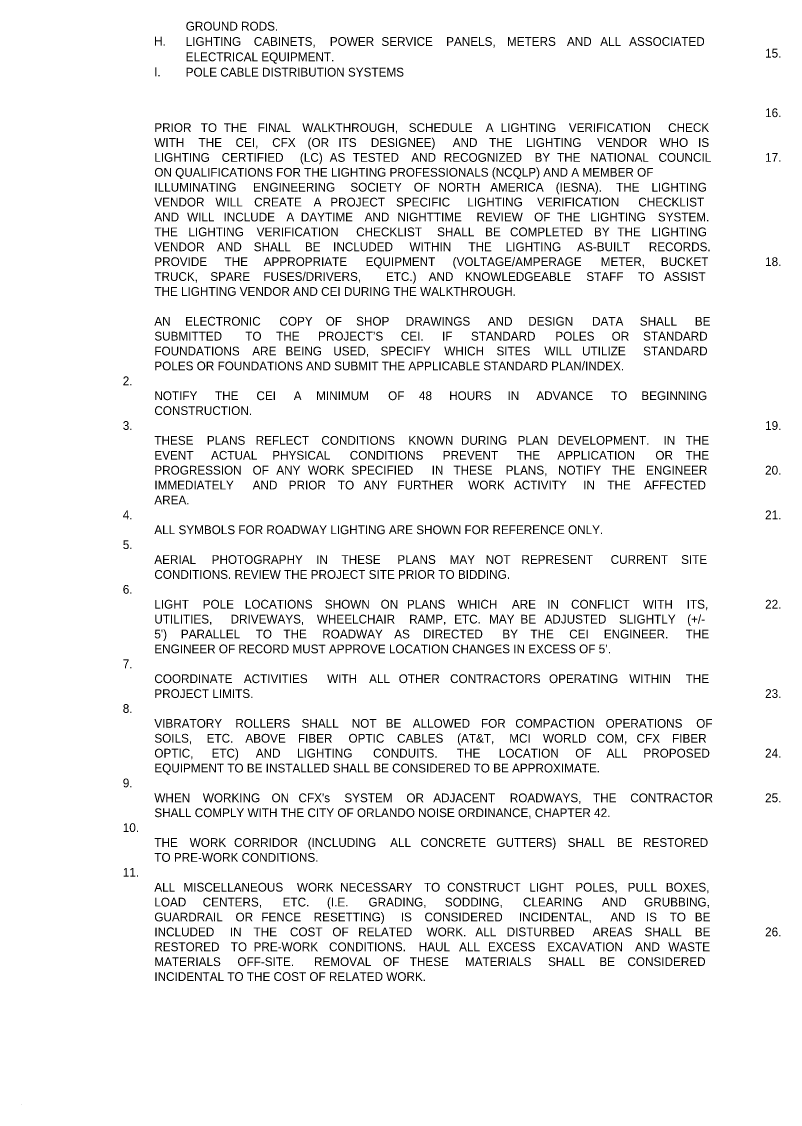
# Model space of a CAD drawing. Extents: x -55 to 2471539, y -90 to 3608906.
# Drawn here: x -55 to 551, y -90 to 775 of the extents above; entities that cross this region are included whole.
import ezdxf

# ---------------------------------------------------------------- set-up
doc = ezdxf.new("R2010")
doc.units = 0
doc.layers.add('TextMinor', color=7, linetype='Continuous')
doc.layers.add('XSCell', color=7, linetype='Continuous')

msp = doc.modelspace()

# ---------------------------------------------------------------- linework, layer by layer
at = {"layer": 'TextMinor'}
msp.add_line((-55, -90), (-55, -90), dxfattribs=at)

# ---------------------------------------------------------------- texts
at = {"layer": 'XSCell'}
for s, p in [('GROUND RODS.', (75.97, 767.96)), ('H.', (50.72, 755.98)), ('LIGHTING ', (75.97, 755.71)), ('CABINETS, ', (130.32, 755.71)), ('POWER ', (191.04, 755.71)), ('SERVICE ', (232.19, 755.71)), ('PANELS, ', (283.88, 755.71)), ('METERS ', (332.46, 755.71)), ('AND ', (380.33, 755.71)), ('ALL ', (406.91, 755.71)), ('ASSOCIATED ', (429.97, 755.71)), ('15.', (538.51, 746.38)), ('ELECTRICAL EQUIPMENT.', (75.97, 743.46)), ('I.', (50.72, 731.48)), ('POLE CABLE DISTRIBUTION SYSTEMS', (75.97, 731.21)), ('16.', (538.51, 698.78)), ('PRIOR ', (50.92, 686.88)), ('TO ', (87.97, 686.88)), ('THE ', (106.26, 686.88)), ('FINAL ', (133.38, 686.88)), ('WALKTHROUGH, ', (169.06, 686.88)), ('SCHEDULE ', (254.01, 686.88)), ('A ', (315.47, 686.88)), ('LIGHTING ', (327.43, 686.88)), ('VERIFICATION ', (381.77, 686.88)), ('CHECK ', (461.12, 686.88)), ('WITH ', (50.92, 674.98)), ('THE ', (86.21, 674.98)), ('CEI, ', (115.75, 674.98)), ('CFX ', (145, 674.98)), ('(OR ', (173.26, 674.98)), ('ITS ', (197.82, 674.98)), ('DESIGNEE) ', (223.77, 674.98)), ('AND ', (289.13, 674.98)), ('THE ', (318.13, 674.98)), ('LIGHTING ', (347.67, 674.98)), ('VENDOR ', (404.44, 674.98)), ('WHO ', (454.24, 674.98)), ('IS ', (484.99, 674.98)), ('LIGHTING ', (50.92, 663.08)), ('CERTIFIED ', (104.66, 663.08)), ('(LC) ', (167.14, 663.08)), ('AS ', (190.89, 663.08)), ('TESTED ', (209.32, 663.08)), ('AND ', (256.04, 663.08)), ('RECOGNIZED ', (282.02, 663.08)), ('BY ', (354.46, 663.08)), ('THE ', (372.41, 663.08)), ('NATIONAL ', (398.92, 663.08)), ('COUNCIL ', (453.39, 663.08)), ('17.', (538.51, 663.08)), ('ON QUALIFICATIONS FOR THE LIGHTING PROFESSIONALS (NCQLP) AND A MEMBER OF ', (50.92, 651.18)), ('ILLUMINATING ', (50.92, 639.28)), ('ENGINEERING ', (129.76, 639.28)), ('SOCIETY ', (207.39, 639.28)), ('OF ', (258.02, 639.28)), ('NORTH ', (277.76, 639.28)), ('AMERICA ', (319.04, 639.28)), ('(IESNA). ', (371.35, 639.28)), ('THE ', (419.56, 639.28)), ('LIGHTING ', (447.79, 639.28)), ('VENDOR ', (50.92, 627.38)), ('WILL ', (99.69, 627.38)), ('CREATE ', (130.61, 627.38)), ('A ', (178.05, 627.38)), ('PROJECT ', (191.4, 627.38)), ('SPECIFIC ', (243.88, 627.38)), ('LIGHTING ', (300.8, 627.38)), ('VERIFICATION ', (356.54, 627.38)), ('CHECKLIST ', (437.29, 627.38)), ('AND ', (50.92, 615.48)), ('WILL ', (77.06, 615.48)), ('INCLUDE ', (106.15, 615.48)), ('A ', (156.37, 615.48)), ('DAYTIME ', (167.89, 615.48)), ('AND ', (218.8, 615.48)), ('NIGHTTIME ', (244.95, 615.48)), ('REVIEW ', (308.14, 615.48)), ('OF ', (354.11, 615.48)), ('THE ', (372.31, 615.48)), ('LIGHTING ', (399, 615.48)), ('SYSTEM. ', (452.91, 615.48)), ('THE ', (50.92, 603.58)), ('LIGHTING ', (78.14, 603.58)), ('VERIFICATION ', (132.59, 603.58)), ('CHECKLIST ', (212.05, 603.58)), ('SHALL ', (276.7, 603.58)), ('BE ', (315.01, 603.58)), ('COMPLETED ', (334.87, 603.58)), ('BY ', (401.91, 603.58)), ('THE ', (420.57, 603.58)), ('LIGHTING ', (447.79, 603.58)), ('VENDOR ', (50.92, 591.68)), ('AND ', (100.99, 591.68)), ('SHALL ', (130.26, 591.68)), ('BE ', (171.16, 591.68)), ('INCLUDED ', (193.6, 591.68)), ('WITHIN ', (254.63, 591.68)), ('THE ', (301.66, 591.68)), ('LIGHTING ', (331.48, 591.68)), ('AS-BUILT ', (388.52, 591.68)), ('RECORDS. ', (445.65, 591.68)), ('PROVIDE ', (50.92, 579.78)), ('THE ', (106.93, 579.78)), ('APPROPRIATE ', (138.23, 579.78)), ('EQUIPMENT ', (219.54, 579.78)), ('(VOLTAGE/AMPERAGE ', (289.04, 579.78)), ('METER, ', (407.26, 579.78)), ('BUCKET ', (455.29, 579.78)), ('18.', (538.51, 579.78)), ('TRUCK, ', (50.92, 567.88)), ('SPARE ', (95.61, 567.88)), ('FUSES/DRIVERS, ', (137.94, 567.88)), ('ETC.) ', (235.78, 567.88)), ('AND ', (269.92, 567.88)), ('KNOWLEDGEABLE ', (298.92, 567.88)), ('STAFF ', (395.78, 567.88)), ('TO ', (437.04, 567.88)), ('ASSIST ', (457.75, 567.88)), ('THE LIGHTING VENDOR AND CEI DURING THE WALKTHROUGH. ', (50.92, 555.98)), ('AN ', (50.92, 532.18)), ('ELECTRONIC ', (75.49, 532.18)), ('COPY ', (150.75, 532.18)), ('OF ', (187.7, 532.18)), ('SHOP ', (212.01, 532.18)), ('DRAWINGS ', (251.62, 532.18)), ('AND ', (317.13, 532.18)), ('DESIGN ', (349.39, 532.18)), ('DATA ', (400.39, 532.18)), ('SHALL ', (438.51, 532.18)), ('BE ', (482.39, 532.18)), ('SUBMITTED ', (50.92, 520.28)), ('TO ', (123.51, 520.28)), ('THE ', (148.15, 520.28)), ('PROJECT’S ', (181.63, 520.28)), ('CEI. ', (247.7, 520.28)), ('IF ', (280.58, 520.28)), ('STANDARD ', (303.72, 520.28)), ('POLES ', (371.09, 520.28)), ('OR ', (415.99, 520.28)), ('STANDARD ', (441.13, 520.28)), ('FOUNDATIONS ', (50.92, 508.38)), ('ARE ', (129.11, 508.38)), ('BEING ', (155.61, 508.38)), ('USED, ', (193.77, 508.38)), ('SPECIFY ', (231.5, 508.38)), ('WHICH ', (282.39, 508.38)), ('SITES ', (324.05, 508.38)), ('WILL ', (362.31, 508.38)), ('UTILIZE ', (392.36, 508.38)), ('STANDARD ', (441.13, 508.38)), ('POLES OR FOUNDATIONS AND SUBMIT THE APPLICABLE STANDARD PLAN/INDEX.', (50.92, 496.48)), ('2.', (25.72, 484.58)), ('NOTIFY ', (50.92, 472.68)), ('THE ', (99.31, 472.68)), ('CEI ', (132.42, 472.68)), ('A ', (162.18, 472.68)), ('MINIMUM ', (180.13, 472.68)), ('OF ', (237.55, 472.68)), ('48 ', (262.17, 472.68)), ('HOURS ', (286.27, 472.68)), ('IN ', (332.9, 472.68)), ('ADVANCE ', (355.9, 472.68)), ('TO ', (415.42, 472.68)), ('BEGINNING ', (439.69, 472.68)), ('CONSTRUCTION.', (50.92, 460.78)), ('3.', (25.72, 448.88)), ('19.', (538.51, 448.88)), ('THESE ', (50.92, 436.98)), ('PLANS ', (92.83, 436.98)), ('REFLECT ', (131.8, 436.98)), ('CONDITIONS ', (184.27, 436.98)), ('KNOWN ', (253.77, 436.98)), ('DURING ', (295.65, 436.98)), ('PLAN ', (340.92, 436.98)), ('DEVELOPMENT. ', (372.81, 436.98)), ('IN ', (457.44, 436.98)), ('THE ', (475.03, 436.98)), ('EVENT ', (50.92, 425.08)), ('ACTUAL ', (96.2, 425.08)), ('PHYSICAL ', (145.08, 425.08)), ('CONDITIONS ', (206.94, 425.08)), ('PREVENT ', (281.18, 425.08)), ('THE ', (340.2, 425.08)), ('APPLICATION ', (372.64, 425.08)), ('OR ', (450.92, 425.08)), ('THE ', (475.03, 425.08)), ('PROGRESSION ', (50.92, 413.18)), ('OF ', (129.35, 413.18)), ('ANY ', (148.35, 413.18)), ('WORK ', (173.54, 413.18)), ('SPECIFIED ', (208.2, 413.18)), ('IN ', (272.35, 413.18)), ('THESE ', (289.73, 413.18)), ('PLANS, ', (331.43, 413.18)), ('NOTIFY ', (373.24, 413.18)), ('THE ', (416.02, 413.18)), ('ENGINEER ', (443.5, 413.18)), ('20.', (538.51, 413.18)), ('IMMEDIATELY ', (50.92, 401.28)), ('AND ', (129.41, 401.28)), ('PRIOR ', (158.2, 401.28)), ('TO ', (197.46, 401.28)), ('ANY ', (217.96, 401.28)), ('FURTHER ', (244.99, 401.28)), ('WORK ', (301.5, 401.28)), ('ACTIVITY ', (338.01, 401.28)), ('IN ', (393.31, 401.28)), ('THE ', (412.53, 401.28)), ('AFFECTED ', (441.86, 401.28)), ('AREA.', (50.92, 389.38)), ('4.', (25.72, 377.48)), ('21.', (538.51, 377.48)), ('ALL SYMBOLS FOR ROADWAY LIGHTING ARE SHOWN FOR REFERENCE ONLY.', (50.92, 365.58)), ('5.', (25.72, 353.68)), ('AERIAL ', (50.92, 341.78)), ('PHOTOGRAPHY ', (96.65, 341.78)), ('IN ', (180.07, 341.78)), ('THESE ', (200.35, 341.78)), ('PLANS ', (244.95, 341.78)), ('MAY ', (286.61, 341.78)), ('NOT ', (315.49, 341.78)), ('REPRESENT ', (343.98, 341.78)), ('CURRENT ', (415.21, 341.78)), ('SITE ', (471.49, 341.78)), ('CONDITIONS. REVIEW THE PROJECT SITE PRIOR TO BIDDING.', (50.92, 329.88)), ('6.', (25.72, 317.98)), ('LIGHT ', (50.92, 306.08)), ('POLE ', (89.54, 306.08)), ('LOCATIONS ', (123.15, 306.08)), ('SHOWN ', (187.03, 306.08)), ('ON ', (231.54, 306.08)), ('PLANS ', (252.54, 306.08)), ('WHICH ', (293.07, 306.08)), ('ARE ', (336.35, 306.08)), ('IN ', (364.47, 306.08)), ('CONFLICT ', (383.63, 306.08)), ('WITH ', (440.93, 306.08)), ('ITS, ', (475.95, 306.08)), ('22.', (538.51, 306.08)), ('UTILITIES, ', (50.92, 294.18)), ('DRIVEWAYS, ', (111.78, 294.18)), ('WHEELCHAIR ', (180.68, 294.18)), ('RAMP, ', (254.36, 294.18)), ('ETC. ', (290.3, 294.18)), ('MAY ', (318.12, 294.18)), ('BE ', (343.19, 294.18)), ('ADJUSTED ', (362.4, 294.18)), ('SLIGHTLY ', (421.83, 294.18)), ('(+/- ', (476.32, 294.18)), ("5') ", (50.92, 282.28)), ('PARALLEL ', (72.07, 282.28)), ('TO ', (131.83, 282.28)), ('THE ', (153.99, 282.28)), ('ROADWAY ', (184.97, 282.28)), ('AS ', (242.43, 282.28)), ('DIRECTED ', (265.33, 282.28)), ('BY ', (328.73, 282.28)), ('THE ', (351.14, 282.28)), ('CEI ', (382.13, 282.28)), ('ENGINEER. ', (409.76, 282.28)), ('THE ', (475.03, 282.28)), ('ENGINEER OF RECORD MUST APPROVE LOCATION CHANGES IN EXCESS OF 5’.', (50.92, 270.38)), ('7.', (25.72, 258.48)), ('COORDINATE ', (50.92, 246.58)), ('ACTIVITIES ', (122.34, 246.58)), ('WITH ', (188.86, 246.58)), ('ALL ', (222.36, 246.58)), ('OTHER ', (246.03, 246.58)), ('CONTRACTORS ', (287.02, 246.58)), ('OPERATING ', (365.99, 246.58)), ('WITHIN ', (430.06, 246.58)), ('THE ', (475.03, 246.58)), ('PROJECT LIMITS.', (50.92, 234.68)), ('23.', (538.51, 234.68)), ('8.', (25.72, 222.78)), ('VIBRATORY ', (50.92, 210.88)), ('ROLLERS ', (115.6, 210.88)), ('SHALL ', (168.44, 210.88)), ('NOT ', (208.51, 210.88)), ('BE ', (235.59, 210.88)), ('ALLOWED ', (257.21, 210.88)), ('FOR ', (311.68, 210.88)), ('COMPACTION ', (339.05, 210.88)), ('OPERATIONS ', (411.16, 210.88)), ('OF ', (483.52, 210.88)), ('SOILS, ', (50.92, 198.98)), ('ETC. ', (92.67, 198.98)), ('ABOVE ', (123.59, 198.98)), ('FIBER ', (165.51, 198.98)), ('OPTIC ', (205.94, 198.98)), ('CABLES ', (244.74, 198.98)), ('(AT&T, ', (292.64, 198.98)), ('MCI ', (334.23, 198.98)), ('WORLD ', (361.13, 198.98)), ('COM, ', (404.06, 198.98)), ('CFX ', (435.87, 198.98)), ('FIBER ', (464.26, 198.98)), ('OPTIC, ', (50.92, 187.08)), ('ETC) ', (96.58, 187.08)), ('AND ', (131.91, 187.08)), ('LIGHTING ', (164.85, 187.08)), ('CONDUITS. ', (225.56, 187.08)), ('THE ', (292.46, 187.08)), ('LOCATION ', (325.94, 187.08)), ('OF ', (386.95, 187.08)), ('ALL ', (411.94, 187.08)), ('PROPOSED ', (441.35, 187.08)), ('24.', (538.51, 187.08)), ('EQUIPMENT TO BE INSTALLED SHALL BE CONSIDERED TO BE APPROXIMATE.', (50.92, 175.18)), ('9.', (25.72, 163.28)), ('WHEN ', (50.92, 151.38)), ('WORKING ', (89.63, 151.38)), ('ON ', (144.47, 151.38)), ("CFX's ", (166, 151.38)), ('SYSTEM ', (202.59, 151.38)), ('OR ', (252.13, 151.38)), ('ADJACENT ', (273.59, 151.38)), ('ROADWAYS, ', (334.69, 151.38)), ('THE ', (401.09, 151.38)), ('CONTRACTOR ', (430.88, 151.38)), ('25.', (538.51, 151.38)), ('SHALL COMPLY WITH THE CITY OF ORLANDO NOISE ORDINANCE, CHAPTER 42.', (50.92, 139.48)), ('10.', (25.72, 127.58)), ('THE ', (50.92, 115.68)), ('WORK ', (79.14, 115.68)), ('CORRIDOR ', (114.54, 115.68)), ('(INCLUDING ', (173.34, 115.68)), ('ALL ', (239.19, 115.68)), ('CONCRETE ', (263.34, 115.68)), ('GUTTERS) ', (323.94, 115.68)), ('SHALL ', (380.9, 115.68)), ('BE ', (420.21, 115.68)), ('RESTORED ', (441.07, 115.68)), ('TO PRE-WORK CONDITIONS.', (50.92, 103.78)), ('11.', (25.72, 91.88)), ('ALL ', (50.92, 79.98)), ('MISCELLANEOUS ', (74.2, 79.98)), ('WORK ', (164.73, 79.98)), ('NECESSARY ', (199.25, 79.98)), ('TO ', (266.17, 79.98)), ('CONSTRUCT ', (284.68, 79.98)), ('LIGHT ', (350.29, 79.98)), ('POLES, ', (386.99, 79.98)), ('PULL ', (428.81, 79.98)), ('BOXES, ', (459.25, 79.98)), ('LOAD ', (50.92, 68.08)), ('CENTERS, ', (89.55, 68.08)), ('ETC. ', (153.33, 68.08)), ('(I.E. ', (188.77, 68.08)), ('GRADING, ', (221.91, 68.08)), ('SODDING, ', (282.85, 68.08)), ('CLEARING ', (345.23, 68.08)), ('AND ', (408.25, 68.08)), ('GRUBBING, ', (441.91, 68.08)), ('GUARDRAIL ', (50.92, 56.18)), ('OR ', (115.72, 56.18)), ('FENCE ', (136.3, 56.18)), ('RESETTING) ', (178.12, 56.18)), ('IS ', (247.66, 56.18)), ('CONSIDERED ', (266.61, 56.18)), ('INCIDENTAL, ', (341.94, 56.18)), ('AND ', (414.99, 56.18)), ('IS ', (443.37, 56.18)), ('TO ', (462.31, 56.18)), ('BE ', (482.39, 56.18)), ('INCLUDED ', (50.92, 44.28)), ('IN ', (111.19, 44.28)), ('THE ', (130.13, 44.28)), ('COST ', (159.19, 44.28)), ('OF ', (193.05, 44.28)), ('RELATED ', (213.61, 44.28)), ('WORK. ', (268.26, 44.28)), ('ALL ', (307.24, 44.28)), ('DISTURBED ', (332.23, 44.28)), ('AREAS ', (400.86, 44.28)), ('SHALL ', (442.26, 44.28)), ('BE ', (482.39, 44.28)), ('26.', (538.51, 44.28)), ('RESTORED ', (50.92, 32.38)), ('TO ', (111.92, 32.38)), ('PRE-WORK ', (130.13, 32.38)), ('CONDITIONS. ', (190.4, 32.38)), ('HAUL ', (262, 32.38)), ('ALL ', (294.21, 32.38)), ('EXCESS ', (317.19, 32.38)), ('EXCAVATION ', (364.68, 32.38)), ('AND ', (434.74, 32.38)), ('WASTE ', (461.25, 32.38)), ('MATERIALS ', (50.92, 20.48)), ('OFF-SITE. ', (117.26, 20.48)), ('REMOVAL ', (178.36, 20.48)), ('OF ', (233.51, 20.48)), ('THESE ', (254.85, 20.48)), ('MATERIALS ', (298.89, 20.48)), ('SHALL ', (365.23, 20.48)), ('BE ', (406.14, 20.48)), ('CONSIDERED ', (428.6, 20.48)), ('INCIDENTAL TO THE COST OF RELATED WORK.', (50.92, 8.58))]:
    msp.add_text(s, height=7, dxfattribs=at).set_placement(p)

doc.saveas('drawing.dxf')
